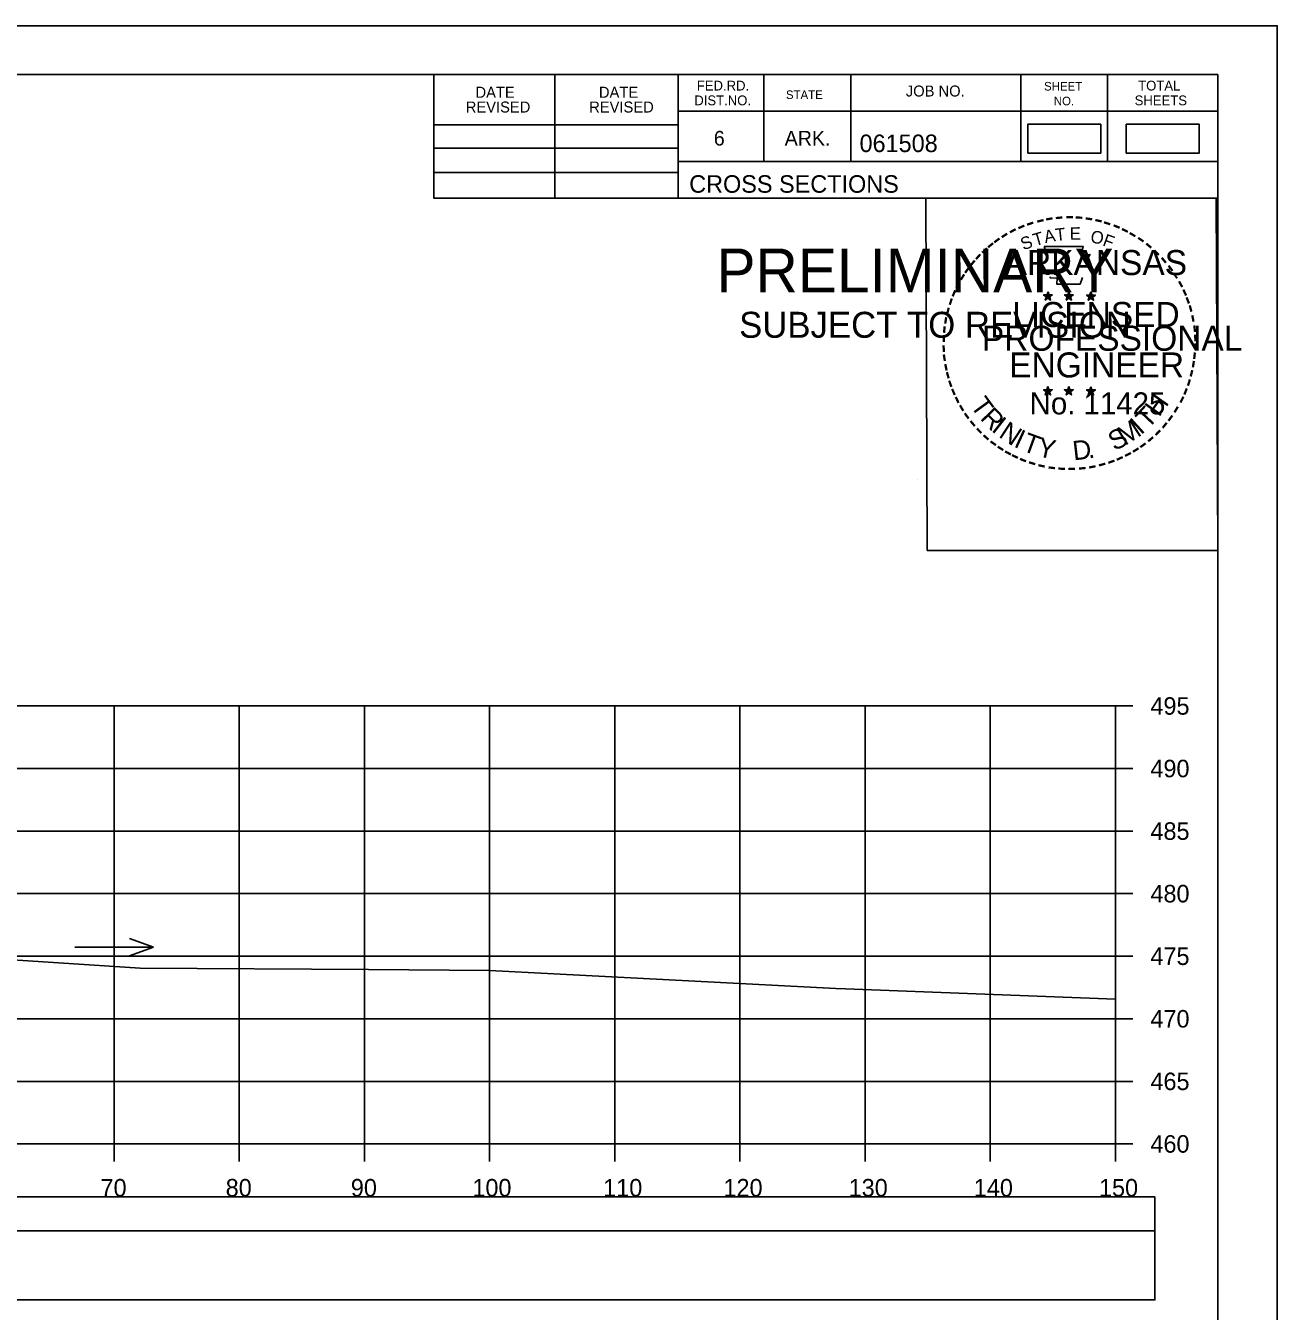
# Model space of a CAD drawing. Extents: x 1371057 to 1372761, y 380005 to 390517.
# Drawn here: x 1371623.8 to 1371723.8, y 382889.1 to 382991.8 of the extents above; entities that cross this region are included whole.
import ezdxf

# ---------------------------------------------------------------- set-up
doc = ezdxf.new("R2010")
doc.units = 0
for name, color, linetype in [('R_Axis', 7, 'Continuous'), ('R_Axis Annot', 7, 'Continuous'), ('R_Border', 7, 'Continuous'), ('R_Border PE', 7, 'Continuous'), ('R_Border Prem', 7, 'Continuous'), ('R_Detour', 7, 'Continuous'), ('R_Dimension', 7, 'Continuous'), ('R_Exist Surface', 7, 'Continuous'), ('R_Grid', 7, 'Continuous'), ('R_No Plot', 7, 'Continuous'), ('R_Water Annot', 7, 'Continuous')]:
    doc.layers.add(name, color=color, linetype=linetype)

msp = doc.modelspace()

# ---------------------------------------------------------------- linework, layer by layer
at = {"layer": 'R_Axis'}
for p, q in [((1371710.87, 382902.45), (1371710.87, 382937.45)), ((1371712.27, 382937.45), (1371710.87, 382937.45)), ((1371712.27, 382932.45), (1371710.87, 382932.45)), ((1371712.27, 382927.45), (1371710.87, 382927.45)), ((1371712.27, 382922.45), (1371710.87, 382922.45)), ((1371712.27, 382917.45), (1371710.87, 382917.45)), ((1371712.27, 382912.45), (1371710.87, 382912.45)), ((1371712.27, 382907.45), (1371710.87, 382907.45)), ((1371410.87, 382902.45), (1371710.87, 382902.45)), ((1371630.87, 382901.05), (1371630.87, 382902.45)), ((1371640.87, 382901.05), (1371640.87, 382902.45)), ((1371650.87, 382901.05), (1371650.87, 382902.45)), ((1371660.87, 382901.05), (1371660.87, 382902.45)), ((1371670.87, 382901.05), (1371670.87, 382902.45)), ((1371680.87, 382901.05), (1371680.87, 382902.45)), ((1371690.87, 382901.05), (1371690.87, 382902.45)), ((1371700.87, 382901.05), (1371700.87, 382902.45)), ((1371710.87, 382901.05), (1371710.87, 382902.45)), ((1371712.27, 382902.45), (1371710.87, 382902.45))]:
    msp.add_line(p, q, dxfattribs=at)
at = {"layer": 'R_Border'}
for p, q in [((1371402.87, 382987.91), (1371719.05, 382987.91)), ((1371656.41, 382978.03), (1371656.41, 382987.91)), ((1371666.09, 382978.03), (1371666.09, 382987.91)), ((1371675.95, 382987.91), (1371675.95, 382978.03)), ((1371682.79, 382987.91), (1371682.79, 382980.97)), ((1371689.73, 382987.91), (1371689.73, 382980.97)), ((1371703.31, 382987.91), (1371703.31, 382980.97)), ((1371710.25, 382987.91), (1371710.25, 382980.97)), ((1371719.05, 382782.45), (1371719.05, 382987.91)), ((1371719.05, 382984.97), (1371675.95, 382984.97)), ((1371719.05, 382984.99), (1371719.05, 382984.99)), ((1371656.41, 382983.89), (1371675.95, 382983.89)), ((1371656.41, 382982.03), (1371675.95, 382982.03)), ((1371656.41, 382980.09), (1371675.95, 382980.09)), ((1371719.05, 382980.97), (1371675.95, 382980.97)), ((1371678.91, 382980.97), (1371719.05, 382980.97)), ((1371719.05, 382978.03), (1371656.41, 382978.03))]:
    msp.add_line(p, q, dxfattribs=at)
at = {"layer": 'R_Border PE'}
for p, q in [((1371705.14, 382970.29), (1371705.49, 382970.18)), ((1371705.14, 382970.29), (1371705.39, 382970.24)), ((1371705.14, 382970.29), (1371705.37, 382970.17)), ((1371705.27, 382969.88), (1371705.49, 382970.18)), ((1371705.27, 382969.88), (1371705.4, 382970.12)), ((1371705.27, 382969.88), (1371705.48, 382970.1)), ((1371705.49, 382970.54), (1371705.45, 382970.29)), ((1371705.7, 382969.88), (1371705.48, 382970.09)), ((1371705.49, 382970.18), (1371705.49, 382970.54)), ((1371705.49, 382970.54), (1371705.54, 382970.29)), ((1371705.83, 382970.29), (1371705.49, 382970.18)), ((1371705.7, 382969.88), (1371705.49, 382970.18)), ((1371705.83, 382970.29), (1371705.55, 382970.24)), ((1371705.7, 382969.88), (1371705.56, 382970.17)), ((1371705.83, 382970.29), (1371705.63, 382970.19)), ((1371706.81, 382970.29), (1371707.16, 382970.18)), ((1371706.81, 382970.29), (1371707.06, 382970.24)), ((1371706.81, 382970.29), (1371707.04, 382970.17)), ((1371706.94, 382969.88), (1371707.16, 382970.18)), ((1371706.94, 382969.88), (1371707.07, 382970.12)), ((1371706.94, 382969.88), (1371707.15, 382970.1)), ((1371707.16, 382970.54), (1371707.12, 382970.29)), ((1371707.37, 382969.88), (1371707.15, 382970.09)), ((1371707.16, 382970.18), (1371707.16, 382970.54)), ((1371707.16, 382970.54), (1371707.21, 382970.29)), ((1371707.5, 382970.29), (1371707.16, 382970.18)), ((1371707.37, 382969.88), (1371707.16, 382970.18)), ((1371707.5, 382970.29), (1371707.22, 382970.24)), ((1371707.37, 382969.88), (1371707.23, 382970.17)), ((1371707.5, 382970.29), (1371707.3, 382970.19)), ((1371708.57, 382970.28), (1371708.92, 382970.17)), ((1371708.57, 382970.28), (1371708.82, 382970.23)), ((1371708.57, 382970.28), (1371708.81, 382970.15)), ((1371708.7, 382969.87), (1371708.92, 382970.17)), ((1371708.7, 382969.87), (1371708.83, 382970.11)), ((1371708.7, 382969.87), (1371708.92, 382970.09)), ((1371708.92, 382970.53), (1371708.88, 382970.28)), ((1371708.92, 382970.17), (1371708.92, 382970.53)), ((1371708.92, 382970.53), (1371708.97, 382970.28)), ((1371709.27, 382970.28), (1371708.92, 382970.17)), ((1371709.13, 382969.87), (1371708.92, 382970.17)), ((1371709.13, 382969.87), (1371708.92, 382970.08)), ((1371709.27, 382970.28), (1371708.98, 382970.23)), ((1371709.13, 382969.87), (1371709, 382970.16)), ((1371709.27, 382970.28), (1371709.06, 382970.17)), ((1371705.13, 382962.72), (1371705.48, 382962.6)), ((1371705.13, 382962.72), (1371705.39, 382962.67)), ((1371705.13, 382962.72), (1371705.37, 382962.59)), ((1371705.27, 382962.31), (1371705.48, 382962.6)), ((1371705.27, 382962.31), (1371705.39, 382962.55)), ((1371705.27, 382962.31), (1371705.48, 382962.52)), ((1371705.48, 382962.97), (1371705.44, 382962.72)), ((1371705.48, 382962.6), (1371705.48, 382962.97)), ((1371705.48, 382962.97), (1371705.53, 382962.72)), ((1371705.83, 382962.72), (1371705.48, 382962.6)), ((1371705.7, 382962.31), (1371705.48, 382962.6)), ((1371705.7, 382962.31), (1371705.48, 382962.52)), ((1371705.83, 382962.72), (1371705.54, 382962.67)), ((1371705.7, 382962.31), (1371705.56, 382962.6)), ((1371705.83, 382962.72), (1371705.63, 382962.61)), ((1371706.8, 382962.72), (1371707.15, 382962.6)), ((1371706.8, 382962.72), (1371707.06, 382962.67)), ((1371706.8, 382962.72), (1371707.04, 382962.59)), ((1371706.94, 382962.31), (1371707.15, 382962.6)), ((1371706.94, 382962.31), (1371707.06, 382962.55)), ((1371706.94, 382962.31), (1371707.15, 382962.52)), ((1371707.15, 382962.97), (1371707.11, 382962.72)), ((1371707.15, 382962.6), (1371707.15, 382962.97)), ((1371707.15, 382962.97), (1371707.2, 382962.72)), ((1371707.5, 382962.72), (1371707.15, 382962.6)), ((1371707.36, 382962.31), (1371707.15, 382962.6)), ((1371707.36, 382962.31), (1371707.15, 382962.52)), ((1371707.5, 382962.72), (1371707.21, 382962.67)), ((1371707.36, 382962.31), (1371707.23, 382962.6)), ((1371707.5, 382962.72), (1371707.29, 382962.61)), ((1371708.57, 382962.71), (1371708.92, 382962.59)), ((1371708.57, 382962.71), (1371708.82, 382962.66)), ((1371708.57, 382962.71), (1371708.81, 382962.58)), ((1371708.7, 382962.3), (1371708.92, 382962.59)), ((1371708.7, 382962.3), (1371708.83, 382962.54)), ((1371708.7, 382962.3), (1371708.92, 382962.51)), ((1371708.92, 382962.96), (1371708.88, 382962.71)), ((1371708.92, 382962.59), (1371708.92, 382962.96)), ((1371708.92, 382962.96), (1371708.97, 382962.71)), ((1371709.27, 382962.71), (1371708.92, 382962.59)), ((1371709.13, 382962.3), (1371708.92, 382962.59)), ((1371709.13, 382962.3), (1371708.92, 382962.51)), ((1371709.27, 382962.71), (1371708.98, 382962.66)), ((1371709.13, 382962.3), (1371708.99, 382962.59)), ((1371709.27, 382962.71), (1371709.06, 382962.6))]:
    msp.add_line(p, q, dxfattribs=at)
for points in [[(1371705.18, 382974.17), (1371705.45, 382973.34)], [(1371708.69, 382973.24), (1371708.83, 382973.53), (1371708.15, 382973.5), (1371708.29, 382974.17), (1371705.18, 382974.17)], [(1371705.67, 382971.74), (1371705.67, 382971.66), (1371706.23, 382971.64), (1371706.18, 382971.16), (1371708.05, 382971.16), (1371708.25, 382971.7)], [(1371705.49, 382970.54), (1371705.7, 382969.88), (1371705.14, 382970.29), (1371705.83, 382970.29), (1371705.27, 382969.88), (1371705.49, 382970.54)], [(1371707.16, 382970.54), (1371707.37, 382969.88), (1371706.81, 382970.29), (1371707.5, 382970.29), (1371706.94, 382969.88), (1371707.16, 382970.54)], [(1371708.92, 382970.53), (1371709.13, 382969.87), (1371708.57, 382970.28), (1371709.27, 382970.28), (1371708.7, 382969.87), (1371708.92, 382970.53)], [(1371705.48, 382962.97), (1371705.7, 382962.31), (1371705.13, 382962.72), (1371705.83, 382962.72), (1371705.27, 382962.31), (1371705.48, 382962.97)], [(1371707.15, 382962.97), (1371707.36, 382962.31), (1371706.8, 382962.72), (1371707.5, 382962.72), (1371706.94, 382962.31), (1371707.15, 382962.97)], [(1371708.92, 382962.96), (1371709.13, 382962.3), (1371708.57, 382962.71), (1371709.27, 382962.71), (1371708.7, 382962.3), (1371708.92, 382962.96)]]:
    msp.add_lwpolyline(points, dxfattribs=at)
for centre, radius in [((1371705.49, 382970.18), 0.172), ((1371705.49, 382970.18), 0.145), ((1371705.49, 382970.18), 0.116), ((1371705.49, 382970.18), 0.0991), ((1371705.49, 382970.18), 0.0747), ((1371705.49, 382970.18), 0.0495), ((1371705.49, 382970.18), 0.0296), ((1371707.16, 382970.18), 0.172), ((1371707.16, 382970.18), 0.145), ((1371707.16, 382970.18), 0.116), ((1371707.16, 382970.18), 0.0991), ((1371707.16, 382970.18), 0.0747), ((1371707.16, 382970.18), 0.0495), ((1371707.16, 382970.18), 0.0296), ((1371708.92, 382970.16), 0.172), ((1371708.92, 382970.16), 0.145), ((1371708.92, 382970.16), 0.116), ((1371708.92, 382970.16), 0.0991), ((1371708.92, 382970.16), 0.0747), ((1371708.92, 382970.16), 0.0495), ((1371708.92, 382970.16), 0.0296), ((1371705.48, 382962.6), 0.172), ((1371705.48, 382962.6), 0.145), ((1371705.48, 382962.6), 0.116), ((1371705.48, 382962.6), 0.0991), ((1371705.48, 382962.6), 0.0747), ((1371705.48, 382962.6), 0.0495), ((1371705.48, 382962.6), 0.0296), ((1371707.15, 382962.6), 0.172), ((1371707.15, 382962.6), 0.145), ((1371707.15, 382962.6), 0.116), ((1371707.15, 382962.6), 0.0991), ((1371707.15, 382962.6), 0.0747), ((1371707.15, 382962.6), 0.0495), ((1371707.15, 382962.6), 0.0296), ((1371708.92, 382962.59), 0.172), ((1371708.92, 382962.59), 0.145), ((1371708.92, 382962.59), 0.116), ((1371708.92, 382962.59), 0.0991), ((1371708.92, 382962.59), 0.0747), ((1371708.92, 382962.59), 0.0495), ((1371708.92, 382962.59), 0.0296)]:
    msp.add_circle(centre, radius, dxfattribs=at)
at = {"layer": 'R_Detour'}
msp.add_lwpolyline([(1371407.72, 382895.5), (1371714.03, 382895.5), (1371714.03, 382898.21), (1371407.72, 382898.21)], close=True, dxfattribs=at)
at = {"layer": 'R_Dimension'}
for points in [[(1371703.87, 382981.63), (1371709.7, 382981.63), (1371709.7, 382983.94), (1371703.87, 382983.94)], [(1371711.74, 382981.63), (1371717.57, 382981.63), (1371717.57, 382983.94), (1371711.74, 382983.94)], [(1371407.72, 382889.98), (1371714.03, 382889.98), (1371714.03, 382895.5), (1371407.72, 382895.5)]]:
    msp.add_lwpolyline(points, close=True, dxfattribs=at)
at = {"layer": 'R_Exist Surface'}
msp.add_lwpolyline([(1371619.88, 382917.34), (1371632.96, 382916.5), (1371651.19, 382916.38), (1371660.88, 382916.32), (1371666, 382916.03), (1371688.53, 382914.86), (1371689.3, 382914.84), (1371710.87, 382914.02)], dxfattribs=at)
at = {"layer": 'R_Grid'}
for p, q in [((1371410.87, 382937.45), (1371710.87, 382937.45)), ((1371630.87, 382902.45), (1371630.87, 382937.45)), ((1371640.87, 382902.45), (1371640.87, 382937.45)), ((1371650.87, 382902.45), (1371650.87, 382937.45)), ((1371660.87, 382902.45), (1371660.87, 382937.45)), ((1371670.87, 382902.45), (1371670.87, 382937.45)), ((1371680.87, 382902.45), (1371680.87, 382937.45)), ((1371690.87, 382902.45), (1371690.87, 382937.45)), ((1371700.87, 382902.45), (1371700.87, 382937.45)), ((1371710.87, 382902.45), (1371710.87, 382937.45)), ((1371410.87, 382932.45), (1371710.87, 382932.45)), ((1371410.87, 382927.45), (1371710.87, 382927.45)), ((1371410.87, 382922.45), (1371710.87, 382922.45)), ((1371410.87, 382917.45), (1371710.87, 382917.45)), ((1371410.87, 382912.45), (1371710.87, 382912.45)), ((1371410.87, 382907.45), (1371710.87, 382907.45)), ((1371410.87, 382902.45), (1371710.87, 382902.45))]:
    msp.add_line(p, q, dxfattribs=at)
at = {"layer": 'R_No Plot'}
for p, q in [((1371390.47, 382991.81), (1371723.8, 382991.81)), ((1371695.09, 382955.58), (1371695.09, 382955.58))]:
    msp.add_line(p, q, dxfattribs=at)
for points in [[(1371390.46, 382991.81), (1371723.8, 382991.81), (1371723.8, 382778.47), (1371390.46, 382778.47)], [(1371636.79, 382987.91), (1371656.41, 382987.91), (1371656.41, 382978.03), (1371672.52, 382978.03), (1371695.72, 382978.03), (1371695.84, 382949.88), (1371719.05, 382949.88), (1371719.05, 382782.45), (1371402.87, 382782.45), (1371402.87, 382987.91)], [(1371695.72, 382978.03), (1371718.93, 382978.03), (1371719.05, 382949.88), (1371695.84, 382949.88)]]:
    msp.add_lwpolyline(points, close=True, dxfattribs=at)
at = {"layer": 'R_Water Annot'}
for p, q in [((1371634.03, 382918.17), (1371632.1, 382918.87)), ((1371627.74, 382918.17), (1371634.03, 382918.17)), ((1371634.03, 382918.17), (1371632.1, 382917.47))]:
    msp.add_line(p, q, dxfattribs=at)

# ---------------------------------------------------------------- texts
at = {"layer": 'R_Axis Annot'}
for s, p in [('495', (1371713.67, 382936.75)), ('490', (1371713.67, 382931.75)), ('485', (1371713.67, 382926.75)), ('480', (1371713.67, 382921.75)), ('475', (1371713.67, 382916.75)), ('470', (1371713.67, 382911.75)), ('465', (1371713.67, 382906.75)), ('460', (1371713.67, 382901.75)), ('70', (1371629.79, 382898.25)), ('80', (1371639.79, 382898.25)), ('90', (1371649.79, 382898.25)), ('100', (1371659.5, 382898.25)), ('110', (1371669.95, 382898.25)), ('120', (1371679.56, 382898.25)), ('130', (1371689.56, 382898.25)), ('140', (1371699.56, 382898.25)), ('150', (1371709.56, 382898.25))]:
    msp.add_text(s, height=1.4, dxfattribs=at).set_placement(p)
at = {"layer": 'R_Border'}
for s, height, p in [('FED.RD.', 0.782, (1371677.43, 382986.63)), ('SHEET', 0.684, (1371705.17, 382986.63)), ('TOTAL', 0.782, (1371712.69, 382986.63)), ('DATE', 0.879, (1371659.75, 382986.05)), ('DATE', 0.879, (1371669.61, 382986.05)), ('DIST.NO.', 0.782, (1371677.23, 382985.45)), ('STATE', 0.684, (1371684.55, 382985.95)), ('JOB NO.', 0.879, (1371694.13, 382986.15)), ('NO.', 0.684, (1371705.95, 382985.45)), ('SHEETS', 0.782, (1371712.41, 382985.45)), ('REVISED', 0.879, (1371658.97, 382984.87)), ('REVISED', 0.879, (1371668.83, 382984.87)), ('6', 1.17, (1371678.79, 382982.23)), ('ARK.', 1.172, (1371684.45, 382982.23)), ('061508', 1.4, (1371690.43, 382981.71)), ('CROSS SECTIONS', 1.4, (1371676.82, 382978.46))]:
    msp.add_text(s, height=height, rotation=360, dxfattribs=at).set_placement(p)
at = {"layer": 'R_Border PE'}
for s, height, rotation, p in [('-', 1.6, 24.3072, (1371703.29, 382975.02)), ('-', 1.6, 19.1761, (1371703.93, 382975.29)), ('-', 1.6, 13.6301, (1371704.68, 382975.53)), ('-', 1.6, 10.2193, (1371705.35, 382975.7)), ('-', 1.6, 5.8968, (1371706.08, 382975.81)), ('-', 1.6, 0.1862, (1371706.86, 382975.88)), ('-', 1.6, 357.743, (1371707.58, 382975.87)), ('-', 1.6, 352.1617, (1371708.32, 382975.81)), ('-', 1.6, 347.2049, (1371709.04, 382975.7)), ('-', 1.6, 342.3362, (1371709.68, 382975.54)), ('-', 1.6, 337.8551, (1371710.41, 382975.32)), ('-', 1.6, 36.2317, (1371701.48, 382973.94)), ('-', 1.6, 34.0636, (1371702.06, 382974.34)), ('-', 1.6, 28.7918, (1371702.66, 382974.71)), ('S', 1, 21.594, (1371703.53, 382973.84)), ('T', 1, 16.4036, (1371704.45, 382974.18)), ('A', 1, 11.2132, (1371705.27, 382974.43)), ('T', 1, 6.0228, (1371706.12, 382974.59)), ('E', 1, 0.8323, (1371707.23, 382974.7)), ('O', 1, 350.4515, (1371708.83, 382974.49)), ('F', 1, 340.0707, (1371709.79, 382974.26)), ('-', 1.6, 334.1211, (1371711.04, 382975.05)), ('-', 1.6, 329.6409, (1371711.62, 382974.76)), ('-', 1.6, 325.8627, (1371712.26, 382974.4)), ('-', 1.6, 42.9622, (1371700.58, 382973.15)), ('-', 1.6, 38.9507, (1371701.01, 382973.56)), ('ARKANSAS', 2, 360, (1371702.03, 382971.88)), ('-', 1.6, 320.5297, (1371712.87, 382973.98)), ('-', 1.6, 315.5786, (1371713.47, 382973.49)), ('-', 1.6, 50.6142, (1371699.72, 382972.18)), ('-', 1.6, 48.423, (1371700.13, 382972.67)), ('-', 1.6, 309.8797, (1371714.04, 382972.94)), ('-', 1.6, 58.0706, (1371698.99, 382971.09)), ('-', 1.6, 54.2325, (1371699.31, 382971.62)), ('-', 1.6, 306.6522, (1371714.57, 382972.34)), ('-', 1.4, 303.6753, (1371715.05, 382971.77)), ('-', 1.6, 62.8713, (1371698.67, 382970.48)), ('-', 1.6, 299.6684, (1371715.37, 382971.16)), ('-', 1.6, 294.6628, (1371715.7, 382970.55)), ('-', 1.6, 72.3945, (1371698.2, 382969.23)), ('-', 1.6, 67.7743, (1371698.41, 382969.86)), ('LICENSED', 2, 360, (1371702.63, 382967.73)), ('DWB', 0.01, 360, (1371705.47, 382970.17)), ('DWB', 0.01, 360, (1371707.14, 382970.17)), ('DWB', 0.01, 360, (1371708.91, 382970.16)), ('-', 1.6, 290.5728, (1371715.95, 382969.97)), ('-', 1.6, 75.461, (1371698, 382968.52)), ('-', 1.6, 285.1233, (1371716.19, 382969.39)), ('-', 1.6, 280.5493, (1371716.39, 382968.65)), ('-', 1.6, 85.1863, (1371697.79, 382967.12)), ('-', 1.6, 81.2013, (1371697.87, 382967.81)), ('PROFESSIONAL', 2, 360, (1371700.21, 382965.83)), ('-', 1.6, 276.5962, (1371716.55, 382967.88)), ('-', 1.6, 89.0622, (1371697.77, 382966.42)), ('-', 1.6, 274.3301, (1371716.61, 382967.16)), ('-', 1.6, 94.1959, (1371697.8, 382965.69)), ('ENGINEER', 2, 360, (1371702.39, 382963.7)), ('-', 1.6, 263.5172, (1371716.62, 382965.86)), ('-', 1.6, 269.9407, (1371716.64, 382966.53)), ('-', 1.6, 98.9479, (1371697.87, 382965.02)), ('-', 1.6, 101.7149, (1371698.01, 382964.29)), ('-', 1.6, 260.9953, (1371716.55, 382965.21)), ('-', 1.6, 105.4578, (1371698.17, 382963.7)), ('-', 1.6, 252.8681, (1371716.26, 382963.81)), ('-', 1.6, 255.7626, (1371716.44, 382964.53)), ('-', 1.6, 109.0874, (1371698.38, 382963.06)), ('-', 1.6, 114.0643, (1371698.64, 382962.47)), ('No. 11425', 1.757, 360, (1371704.02, 382960.75)), ('DWB', 0.01, 360, (1371705.47, 382962.6)), ('DWB', 0.01, 360, (1371707.14, 382962.6)), ('DWB', 0.01, 360, (1371708.91, 382962.59)), ('-', 1.6, 247.8887, (1371716.04, 382963.14)), ('-', 1.6, 115.7289, (1371698.94, 382961.85)), ('-', 1.6, 120.4471, (1371699.3, 382961.26)), ('T', 1.54, 306.0406, (1371699.24, 382961.44)), ('H', 1.54, 54.6088, (1371714.36, 382960.48)), ('-', 1.6, 244.6197, (1371715.78, 382962.51)), ('-', 1.6, 125.8934, (1371699.7, 382960.7)), ('R', 1.54, 314.005, (1371700, 382960.39)), ('I', 1.54, 321.9694, (1371700.9, 382959.46)), ('I', 1.54, 42.1136, (1371712.91, 382959.06)), ('T', 1.54, 46.6444, (1371713.47, 382959.54)), ('-', 1.6, 233.8452, (1371714.98, 382961.1)), ('-', 1.6, 239.0712, (1371715.38, 382961.76)), ('-', 1.6, 130.7181, (1371700.17, 382960.15)), ('-', 1.6, 134.2238, (1371700.68, 382959.61)), ('N', 1.54, 326.5002, (1371701.47, 382958.99)), ('I', 1.54, 335.3603, (1371702.68, 382958.2)), ('S', 1.54, 26.9312, (1371710.79, 382957.8)), ('M', 1.54, 32.6563, (1371711.63, 382958.21)), ('-', 1.6, 225.7653, (1371714.07, 382959.97)), ('-', 1.6, 231.2538, (1371714.55, 382960.54)), ('-', 1.6, 138.9338, (1371701.21, 382959.14)), ('-', 1.6, 144.6463, (1371701.76, 382958.74)), ('T', 1.54, 339.8912, (1371703.34, 382957.88)), ('Y', 1.54, 347.8556, (1371704.56, 382957.43)), ('D', 1.54, 6.3969, (1371707.54, 382957.07)), ('-', 1.6, 215.7363, (1371713, 382958.99)), ('-', 1.6, 221.0851, (1371713.55, 382959.46)), ('-', 1.6, 148.0898, (1371702.32, 382958.37)), ('-', 1.6, 151.5704, (1371702.9, 382958.04)), ('-', 1.6, 154.6002, (1371703.43, 382957.79)), ('.', 1.54, 13.7642, (1371708.74, 382957.2)), ('-', 1.6, 204.2516, (1371711.29, 382957.94)), ('-', 1.6, 207.3568, (1371711.91, 382958.26)), ('-', 1.6, 212.2491, (1371712.47, 382958.61)), ('-', 1.6, 158.5612, (1371704.05, 382957.54)), ('-', 1.6, 162.7983, (1371704.74, 382957.33)), ('-', 1.6, 167.5555, (1371705.45, 382957.16)), ('-', 1.6, 173.1155, (1371706.22, 382957.05)), ('-', 1.6, 176.5183, (1371706.97, 382957)), ('-', 1.6, 181.5918, (1371707.72, 382957.02)), ('-', 1.6, 185.8167, (1371708.52, 382957.09)), ('-', 1.6, 191.2858, (1371709.26, 382957.23)), ('-', 1.6, 195.4743, (1371709.99, 382957.43)), ('-', 1.6, 200.7184, (1371710.67, 382957.67))]:
    msp.add_text(s, height=height, rotation=rotation, dxfattribs=at).set_placement(p)
at = {"layer": 'R_Border Prem'}
for s, height, p in [('PRELIMINARY', 3.5, (1371679, 382970.5)), ('DWB', 0.01, (1371679.75, 382972.35)), ('SUBJECT TO REVISION', 2.0751, (1371680.81, 382966.87))]:
    msp.add_text(s, height=height, rotation=360, dxfattribs=at).set_placement(p)

doc.saveas('drawing.dxf')
